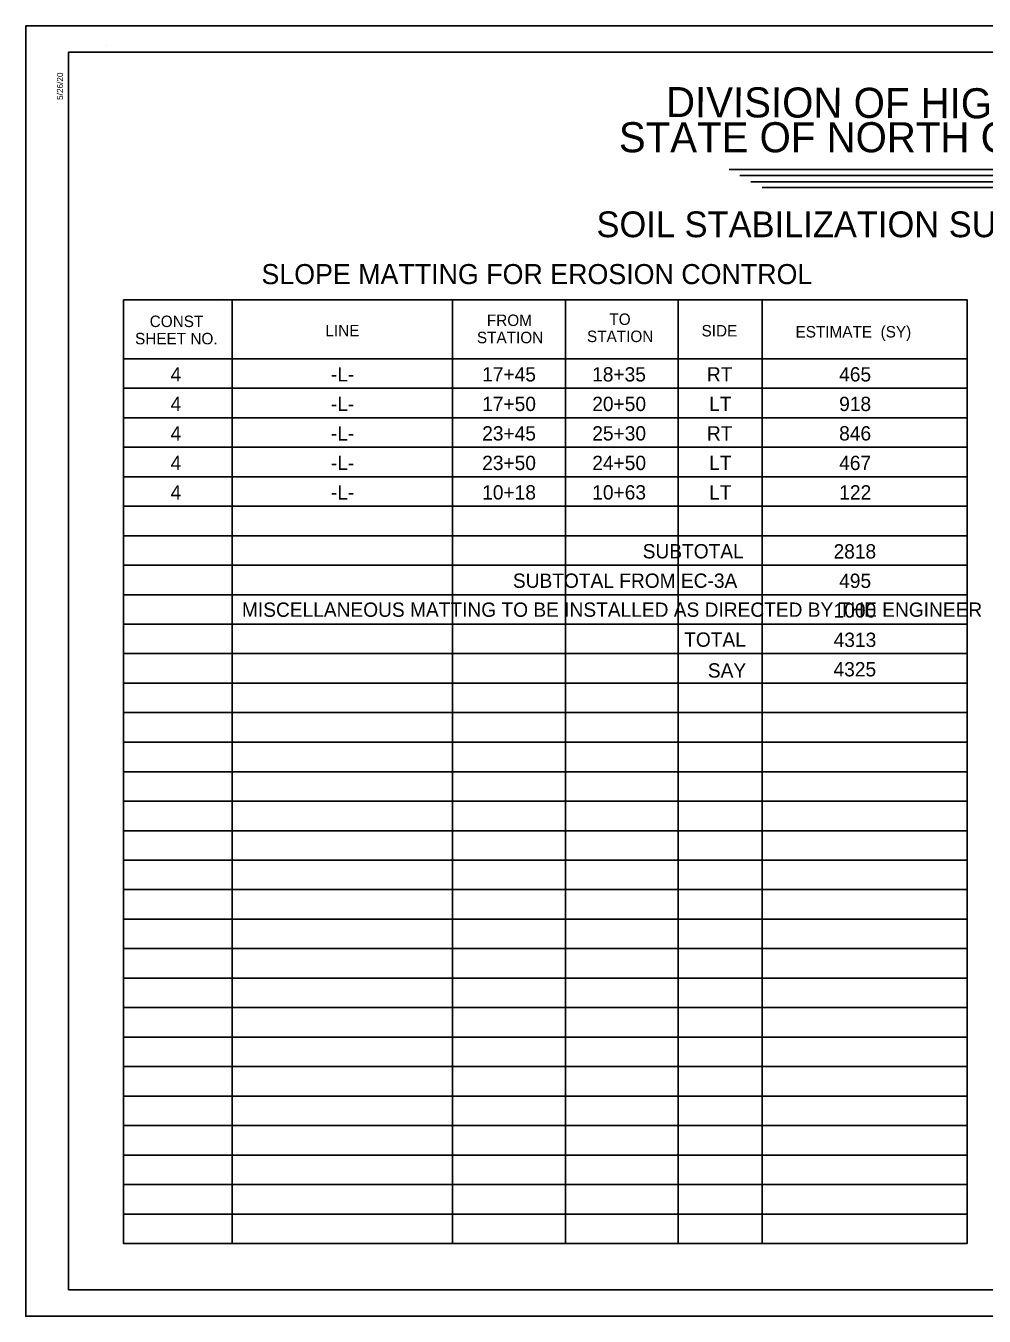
# Model space of a CAD drawing. Extents: x 1674550 to 1676250, y 1328139 to 1330492.
# Drawn here: x 1674550 to 1675367, y 1328139 to 1329239 of the extents above; entities that cross this region are included whole.
import ezdxf

# ---------------------------------------------------------------- set-up
doc = ezdxf.new("R2010")
doc.units = 0
for name, color, linetype in [('Blank Plan Sheet Both CELL', 7, 'Continuous'), ('Matting Summary Sheet CELL', 7, 'Continuous'), ('Sheet Data Field CELL', 7, 'Continuous'), ('Sheet Plan CELL', 7, 'Continuous'), ('Sheet Plot Border Outside CELL', 7, 'Continuous'), ('z - Construction', 7, 'Continuous')]:
    doc.layers.add(name, color=color, linetype=linetype)

msp = doc.modelspace()

# ---------------------------------------------------------------- linework, layer by layer
at = {"layer": 'Blank Plan Sheet Both CELL'}
msp.add_line((1674618.7, 1329221.9), (1674618.7, 1329221.9), dxfattribs=at)
at = {"layer": 'Matting Summary Sheet CELL'}
for p, q in [((1675149.8, 1329116.5), (1675570.9, 1329116.5)), ((1675159, 1329111.4), (1675561.3, 1329111.4)), ((1675168.2, 1329105.9), (1675551.7, 1329105.9)), ((1675177.8, 1329101), (1675542, 1329101)), ((1674717.2, 1329006.8), (1674717.2, 1329006.8)), ((1674725.9, 1329005.3), (1674725.9, 1328200.9)), ((1674913.8, 1329005.3), (1674913.8, 1328200.9)), ((1675010.1, 1329005.3), (1675010.1, 1328200.9)), ((1675106.4, 1329005.3), (1675106.4, 1328200.9)), ((1675177.8, 1329005.3), (1675177.8, 1328200.9)), ((1674633.1, 1328955), (1675352.8, 1328955)), ((1674633.1, 1328929.9), (1675352.8, 1328929.9)), ((1674633.1, 1328904.8), (1675352.8, 1328904.8)), ((1674633.1, 1328879.6), (1675352.8, 1328879.6)), ((1674633.1, 1328854.5), (1675352.8, 1328854.5)), ((1674633.1, 1328829.4), (1675352.8, 1328829.4)), ((1674633.1, 1328804.2), (1675352.8, 1328804.2)), ((1674633.1, 1328779.1), (1675352.8, 1328779.1)), ((1674633.1, 1328753.9), (1675352.8, 1328753.9)), ((1674633.1, 1328728.8), (1675352.8, 1328728.8)), ((1674633.1, 1328703.7), (1675352.8, 1328703.7)), ((1674633.1, 1328678.5), (1675352.8, 1328678.5)), ((1674633.1, 1328653.4), (1675352.8, 1328653.4)), ((1674633.1, 1328628.2), (1675352.8, 1328628.2)), ((1674633.1, 1328603.1), (1675352.8, 1328603.1)), ((1674633.1, 1328578), (1675352.8, 1328578)), ((1674633.1, 1328552.8), (1675352.8, 1328552.8)), ((1674633.1, 1328527.7), (1675352.8, 1328527.7)), ((1674633.1, 1328502.6), (1675352.8, 1328502.6)), ((1674633.1, 1328477.4), (1675352.8, 1328477.4)), ((1674633.1, 1328452.3), (1675352.8, 1328452.3)), ((1674633.1, 1328427.1), (1675352.8, 1328427.1)), ((1674633.1, 1328402), (1675352.8, 1328402)), ((1674633.1, 1328376.9), (1675352.8, 1328376.9)), ((1674633.1, 1328351.7), (1675352.8, 1328351.7)), ((1674633.1, 1328326.6), (1675352.8, 1328326.6)), ((1674633.1, 1328301.5), (1675352.8, 1328301.5)), ((1674633.1, 1328276.3), (1675352.8, 1328276.3)), ((1674633.1, 1328251.2), (1675352.8, 1328251.2)), ((1674633.1, 1328226), (1675352.8, 1328226))]:
    msp.add_line(p, q, dxfattribs=at)
msp.add_lwpolyline([(1674633.1, 1329005.3), (1675352.8, 1329005.3), (1675352.8, 1328200.9), (1674633.1, 1328200.9)], close=True, dxfattribs=at)
at = {"layer": 'Sheet Data Field CELL'}
msp.add_line((1674549.8, 1328138.9), (1674549.8, 1328138.9), dxfattribs=at)
at = {"layer": 'Sheet Plan CELL'}
for p, q in [((1674586.3, 1328161.4), (1674586.3, 1329216.4)), ((1676236.3, 1329216.4), (1674586.3, 1329216.4)), ((1674586.3, 1328161.4), (1676236.3, 1328161.4)), ((1674616.2, 1328161.4), (1674616.2, 1328161.4))]:
    msp.add_line(p, q, dxfattribs=at)
at = {"layer": 'Sheet Plot Border Outside CELL'}
msp.add_lwpolyline([(1674549.8, 1329238.9), (1676249.8, 1329238.9), (1676249.8, 1328138.9), (1674549.8, 1328138.9)], close=True, dxfattribs=at)
at = {"layer": 'z - Construction'}
for p, q in [((1676249.8, 1329238.9), (1674549.8, 1329238.9)), ((1674549.8, 1329238.9), (1674549.8, 1328138.9)), ((1674549.8, 1328138.9), (1676249.8, 1328138.9))]:
    msp.add_line(p, q, dxfattribs=at)

# ---------------------------------------------------------------- texts
at = {"layer": 'Matting Summary Sheet CELL'}
for s, height, rotation, p in [('  DIVISION OF HIGHWAYS', 25.64, 359.7699, (1675076.8, 1329161.2)), ('STATE OF NORTH CAROLINA', 25.64, 360, (1675055.7, 1329131.1)), ('SOIL STABILIZATION SUMMARY SHEET', 21.977, 360, (1675036.6, 1329058.7)), ('SLOPE MATTING FOR EROSION CONTROL', 17.093, 360, (1674750.8, 1329018.7)), ('CONST', 9.77, 360, (1674655.5, 1328982.1)), ('LINE', 9.76, 360, (1674805.4, 1328974.2)), ('FROM ', 9.77, 360, (1674943.1, 1328983)), ('TO', 9.77, 360, (1675047.6, 1328983.9)), ('SIDE', 9.76, 360, (1675126.2, 1328974.1)), ('SHEET NO.', 9.77, 360, (1674643, 1328967.4)), ('STATION', 9.77, 360, (1674934.6, 1328968.3)), ('STATION', 9.77, 360, (1675028.5, 1328969.3)), ('ESTIMATE  (SY)', 9.763, 360, (1675206.4, 1328973.2)), ('4', 12.2, 360, (1674673.3, 1328935.7)), ('-L-', 12.21, 360, (1674810.1, 1328935.7)), ('17+45', 12.21, 360, (1674939.1, 1328935.7)), ('18+35', 12.21, 360, (1675032.9, 1328935.7)), ('RT', 12.21, 360, (1675130.8, 1328935.7)), ('465', 12.21, 360, (1675243.6, 1328935.7)), ('4', 12.2, 360, (1674673.3, 1328910.5)), ('-L-', 12.21, 360, (1674810.1, 1328910.5)), ('17+50', 12.21, 360, (1674939.1, 1328910.5)), ('20+50', 12.21, 360, (1675033, 1328910.5)), ('LT', 12.21, 360, (1675132.7, 1328910.5)), ('918', 12.21, 360, (1675243.6, 1328910.5)), ('4', 12.2, 360, (1674673.3, 1328885.4)), ('-L-', 12.21, 360, (1674810.1, 1328885.4)), ('23+45', 12.21, 360, (1674939.1, 1328885.4)), ('25+30', 12.21, 360, (1675033, 1328885.4)), ('RT', 12.21, 360, (1675130.8, 1328885.4)), ('846', 12.21, 360, (1675243.6, 1328885.4)), ('4', 12.2, 360, (1674673.3, 1328860.2)), ('-L-', 12.21, 360, (1674810.1, 1328860.2)), ('23+50', 12.21, 360, (1674939.1, 1328860.2)), ('24+50', 12.21, 360, (1675033, 1328860.2)), ('LT', 12.21, 360, (1675132.7, 1328860.2)), ('467', 12.21, 360, (1675243.6, 1328860.2)), ('4', 12.2, 360, (1674673.3, 1328835.1)), ('-L-', 12.21, 360, (1674810.1, 1328835.1)), ('10+18', 12.21, 360, (1674939.1, 1328835.1)), ('10+63', 12.21, 360, (1675033, 1328835.1)), ('LT', 12.21, 360, (1675132.7, 1328835.1)), ('122', 12.21, 360, (1675243.7, 1328835.1)), ('SUBTOTAL', 12.21, 360, (1675076, 1328784.9)), ('2818', 12.21, 360, (1675238.8, 1328784.8)), ('SUBTOTAL FROM EC-3A', 12.209, 360, (1674965.3, 1328759.8)), ('495', 12.21, 360, (1675243.6, 1328759.7)), ('MISCELLANEOUS MATTING TO BE INSTALLED AS DIRECTED BY THE ENGINEER', 12.209, 360, (1674734.2, 1328735.1)), ('1000', 12.21, 360, (1675238.9, 1328734.5)), ('TOTAL', 12.21, 360, (1675111.4, 1328709.6)), ('4313', 12.21, 360, (1675238.9, 1328709.4)), ('SAY', 12.21, 360, (1675131.6, 1328683.3)), ('4325', 12.21, 360, (1675238.8, 1328684.3))]:
    msp.add_text(s, height=height, rotation=rotation, dxfattribs=at).set_placement(p)
at = {"layer": 'Sheet Plan CELL'}
msp.add_text('5/26/20', height=5.25, rotation=90, dxfattribs=at).set_placement((1674581.6, 1329175.7))

doc.saveas('drawing.dxf')
